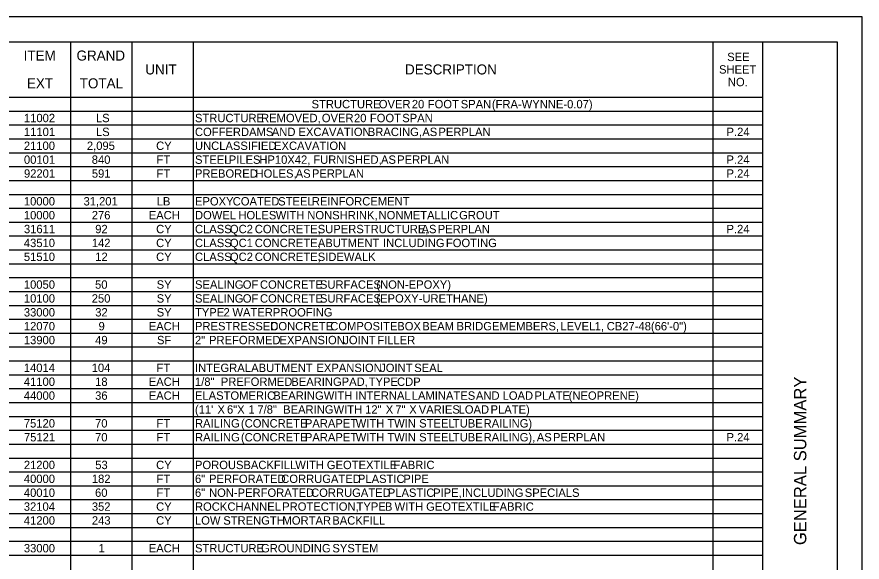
# Model space of a CAD drawing. Extents: x 0 to 34, y 0 to 22.
# Drawn here: x 16.94 to 34, y 11 to 22 of the extents above; entities that cross this region are included whole.
import ezdxf

# ---------------------------------------------------------------- set-up
doc = ezdxf.new("R2010")
doc.units = 0
for name, color, linetype in [('SH_Border', 7, 'Continuous'), ('SH_Cut_Line', 7, 'Continuous'), ('SH_Data', 7, 'Continuous')]:
    doc.layers.add(name, color=color, linetype=linetype)

msp = doc.modelspace()

# ---------------------------------------------------------------- linework, layer by layer
at = {"layer": 'SH_Border'}
msp.add_line((32, 0.5), (32, 21.5), dxfattribs=at)
msp.add_lwpolyline([(1.5, 21.5), (33.5, 21.5), (33.5, 0.5), (1.5, 0.5)], close=True, dxfattribs=at)
at = {"layer": 'SH_Cut_Line'}
msp.add_lwpolyline([(0, 0), (34, 0), (34, 22), (0, 22)], close=True, dxfattribs=at)
at = {"layer": 'SH_Data'}
for p, q in [((16.799, 21.5), (19.27, 21.5)), ((18.035, 0.502), (18.035, 21.5)), ((19.27, 21.5), (20.505, 21.5)), ((19.27, 0.502), (19.27, 21.5)), ((20.505, 21.5), (30.995, 21.5)), ((20.505, 0.502), (20.505, 21.5)), ((30.995, 21.5), (32, 21.5)), ((30.995, 0.502), (30.995, 21.5)), ((32, 0.502), (32, 21.5)), ((13.555, 20.38), (32, 20.38)), ((19.27, 20.38), (32, 20.38)), ((1.5, 20.1), (32, 20.1)), ((1.5, 19.82), (32, 19.82)), ((1.5, 19.54), (32, 19.54)), ((1.5, 19.26), (32, 19.26)), ((1.5, 18.98), (32, 18.98)), ((1.5, 18.7), (32, 18.7)), ((1.5, 18.42), (32, 18.42)), ((1.5, 18.14), (32, 18.14)), ((1.5, 17.86), (32, 17.86)), ((1.5, 17.58), (32, 17.58)), ((1.5, 17.3), (32, 17.3)), ((1.5, 17.021), (32, 17.021)), ((1.5, 16.741), (32, 16.741)), ((1.5, 16.461), (32, 16.461)), ((1.5, 16.181), (32, 16.181)), ((1.5, 15.901), (32, 15.901)), ((1.5, 15.621), (32, 15.621)), ((1.5, 15.341), (32, 15.341)), ((1.5, 15.061), (32, 15.061)), ((1.5, 14.781), (32, 14.781)), ((1.5, 14.501), (32, 14.501)), ((1.5, 14.221), (32, 14.221)), ((1.5, 13.941), (32, 13.941)), ((1.5, 13.661), (32, 13.661)), ((1.5, 13.381), (32, 13.381)), ((1.5, 13.101), (32, 13.101)), ((1.5, 12.821), (32, 12.821)), ((1.5, 12.541), (32, 12.541)), ((1.5, 12.261), (32, 12.261)), ((1.5, 11.981), (32, 11.981)), ((1.5, 11.701), (32, 11.701)), ((1.5, 11.421), (32, 11.421)), ((1.5, 11.141), (32, 11.141))]:
    msp.add_line(p, q, dxfattribs=at)

# ---------------------------------------------------------------- texts
for s, height, p in [('ITEM', 0.2027, (17.081, 21.119)), ('GRAND', 0.2027, (18.148, 21.119)), ('SEE', 0.1689, (31.278, 21.109)), ('UNIT', 0.2027, (19.536, 20.839)), ('DESCRIPTION', 0.20269, (24.777, 20.839)), ('SHEET', 0.1689, (31.113, 20.856)), ('EXT', 0.2027, (17.147, 20.559)), ('TOTAL', 0.2027, (18.213, 20.559)), ('NO.', 0.1689, (31.292, 20.602)), ('STRUCTURE', 0.1689, (22.891, 20.156)), (' OVER', 0.1689, (24.185, 20.156)), (' 20', 0.1689, (24.851, 20.156)), (' FOOT', 0.1689, (25.173, 20.156)), (' SPAN', 0.1689, (25.838, 20.156)), (' (FRA-WYNNE-0.07)', 0.16891, (26.466, 20.156)), ('11002', 0.1689, (17.087, 19.876)), ('LS', 0.1689, (18.54, 19.876)), ('STRUCTURE', 0.1689, (20.538, 19.876)), (' REMOVED,', 0.1689, (21.808, 19.876)), (' OVER', 0.1689, (23.035, 19.876)), (' 20', 0.1689, (23.684, 19.876)), (' FOOT', 0.1689, (24.005, 19.876)), (' SPAN', 0.1689, (24.658, 19.876)), ('11101', 0.1689, (17.087, 19.596)), ('LS', 0.1689, (18.54, 19.596)), ('COFFERDAMS', 0.1689, (20.538, 19.596)), (' AND', 0.1689, (22.026, 19.596)), (' EXCAVATION', 0.16891, (22.564, 19.596)), (' BRACING,', 0.1689, (23.963, 19.596)), (' AS', 0.1689, (25.062, 19.596)), (' PER', 0.1689, (25.388, 19.596)), (' PLAN', 0.1689, (25.85, 19.596)), ('P.24', 0.1689, (31.264, 19.596)), ('21100', 0.1689, (17.085, 19.316)), ('2,095', 0.1689, (18.357, 19.316)), ('CY', 0.1689, (19.754, 19.316)), ('UNCLASSIFIED', 0.16891, (20.538, 19.316)), (' EXCAVATION', 0.16891, (22.071, 19.316)), ('00101', 0.1689, (17.087, 19.036)), ('840', 0.1689, (18.455, 19.036)), ('FT', 0.1689, (19.762, 19.036)), ('STEEL', 0.1689, (20.538, 19.036)), (' PILES', 0.1689, (21.157, 19.036)), (' HP10X42,', 0.1689, (21.774, 19.036)), (' FURNISHED,', 0.16891, (22.863, 19.036)), (' AS', 0.1689, (24.229, 19.036)), (' PER', 0.1689, (24.556, 19.036)), (' PLAN', 0.1689, (25.018, 19.036)), ('P.24', 0.1689, (31.264, 19.036)), ('92201', 0.1689, (17.087, 18.756)), ('591', 0.1689, (18.457, 18.756)), ('FT', 0.1689, (19.762, 18.756)), ('PREBORED', 0.1689, (20.538, 18.756)), (' HOLES,', 0.1689, (21.697, 18.756)), (' AS', 0.1689, (22.508, 18.756)), (' PER', 0.1689, (22.835, 18.756)), (' PLAN', 0.1689, (23.297, 18.756)), ('P.24', 0.1689, (31.264, 18.756)), ('10000', 0.1689, (17.085, 18.196)), ('31,201', 0.1689, (18.289, 18.196)), ('LB', 0.1689, (19.765, 18.196)), ('EPOXY', 0.1689, (20.538, 18.196)), (' COATED', 0.1689, (21.237, 18.196)), (' STEEL', 0.1689, (22.154, 18.196)), (' REINFORCEMENT', 0.16891, (22.834, 18.196)), ('10000', 0.1689, (17.085, 17.916)), ('276', 0.1689, (18.455, 17.916)), ('EACH', 0.1689, (19.605, 17.916)), ('DOWEL', 0.1689, (20.538, 17.916)), (' HOLES', 0.1689, (21.351, 17.916)), (' WITH', 0.1689, (22.105, 17.916)), (' NONSHRINK,', 0.16891, (22.742, 17.916)), (' NONMETALLIC', 0.16891, (24.18, 17.916)), (' GROUT', 0.1689, (25.806, 17.916)), ('31611', 0.1689, (17.087, 17.636)), ('92', 0.1689, (18.525, 17.636)), ('CY', 0.1689, (19.754, 17.636)), ('CLASS', 0.1689, (20.538, 17.636)), (' QC2', 0.1689, (21.18, 17.636)), (' CONCRETE,', 0.1689, (21.682, 17.636)), (' SUPERSTRUCTURE,', 0.16891, (22.953, 17.636)), (' AS', 0.1689, (25.047, 17.636)), (' PER', 0.1689, (25.374, 17.636)), (' PLAN', 0.1689, (25.836, 17.636)), ('P.24', 0.1689, (31.264, 17.636)), ('43510', 0.1689, (17.085, 17.356)), ('142', 0.1689, (18.457, 17.356)), ('CY', 0.1689, (19.754, 17.356)), ('CLASS', 0.1689, (20.538, 17.356)), (' QC1', 0.1689, (21.18, 17.356)), (' CONCRETE,', 0.1689, (21.682, 17.356)), (' ABUTMENT', 0.1689, (22.954, 17.356)), (' INCLUDING', 0.1689, (24.27, 17.356)), (' FOOTING', 0.1689, (25.539, 17.356)), ('51510', 0.1689, (17.085, 17.076)), ('12', 0.1689, (18.525, 17.076)), ('CY', 0.1689, (19.754, 17.076)), ('CLASS', 0.1689, (20.538, 17.076)), (' QC2', 0.1689, (21.18, 17.076)), (' CONCRETE,', 0.1689, (21.682, 17.076)), (' SIDEWALK', 0.1689, (22.953, 17.076)), ('10050', 0.1689, (17.085, 16.516)), ('50', 0.1689, (18.522, 16.516)), ('SY', 0.1689, (19.765, 16.516)), ('SEALING', 0.1689, (20.538, 16.516)), (' OF', 0.1689, (21.44, 16.516)), (' CONCRETE', 0.1689, (21.787, 16.516)), (' SURFACES', 0.1689, (22.997, 16.516)), (' (NON-EPOXY)', 0.16891, (24.136, 16.516)), ('10100', 0.1689, (17.085, 16.236)), ('250', 0.1689, (18.455, 16.236)), ('SY', 0.1689, (19.765, 16.236)), ('SEALING', 0.1689, (20.538, 16.236)), (' OF', 0.1689, (21.44, 16.236)), (' CONCRETE', 0.1689, (21.787, 16.236)), (' SURFACES', 0.1689, (22.997, 16.236)), (' (EPOXY-URETHANE)', 0.16891, (24.136, 16.236)), ('33000', 0.1689, (17.085, 15.956)), ('32', 0.1689, (18.525, 15.956)), ('SY', 0.1689, (19.765, 15.956)), ('TYPE', 0.1689, (20.538, 15.956)), (' 2', 0.1689, (21.051, 15.956)), (' WATERPROOFING', 0.16891, (21.231, 15.956)), ('12070', 0.1689, (17.085, 15.676)), ('9', 0.169, (18.592, 15.676)), ('EACH', 0.1689, (19.605, 15.676)), ('PRESTRESSED', 0.16891, (20.538, 15.676)), (' CONCRETE', 0.1689, (21.995, 15.676)), (' COMPOSITE', 0.1689, (23.205, 15.676)), (' BOX', 0.1689, (24.557, 15.676)), (' BEAM', 0.1689, (25.062, 15.676)), (' BRIDGE', 0.1689, (25.753, 15.676)), (' MEMBERS,', 0.1689, (26.617, 15.676)), (' LEVEL', 0.1689, (27.849, 15.676)), (' 1,', 0.1689, (28.541, 15.676)), (' CB27-48(66\'-0")', 0.16891, (28.784, 15.676)), ('13900', 0.1689, (17.085, 15.396)), ('49', 0.1689, (18.524, 15.396)), ('SF', 0.1689, (19.771, 15.396)), ('2"', 0.1689, (20.538, 15.396)), (' PREFORMED', 0.1689, (20.759, 15.396)), (' EXPANSION', 0.1689, (22.181, 15.396)), (' JOINT', 0.1689, (23.468, 15.396)), (' FILLER', 0.1689, (24.155, 15.396)), ('14014', 0.1689, (17.084, 14.836)), ('104', 0.1689, (18.454, 14.836)), ('FT', 0.1689, (19.762, 14.836)), ('INTEGRAL', 0.1689, (20.538, 14.836)), (' ABUTMENT', 0.1689, (21.609, 14.836)), (' EXPANSION', 0.1689, (22.926, 14.836)), (' JOINT', 0.1689, (24.212, 14.836)), (' SEAL', 0.1689, (24.9, 14.836)), ('41100', 0.1689, (17.085, 14.556)), ('18', 0.1689, (18.523, 14.556)), ('EACH', 0.1689, (19.605, 14.556)), ('1/8"', 0.1689, (20.538, 14.556)), (' PREFORMED', 0.1689, (20.997, 14.556)), (' BEARING', 0.1689, (22.419, 14.556)), (' PAD,', 0.1689, (23.436, 14.556)), (' TYPE', 0.1689, (23.98, 14.556)), (' CDP', 0.1689, (24.553, 14.556)), ('44000', 0.1689, (17.085, 14.276)), ('36', 0.1689, (18.523, 14.276)), ('EACH', 0.1689, (19.605, 14.276)), ('ELASTOMERIC', 0.16891, (20.538, 14.276)), (' BEARING', 0.1689, (22.056, 14.276)), (' WITH', 0.1689, (23.074, 14.276)), (' INTERNAL', 0.1689, (23.711, 14.276)), (' LAMINATES', 0.1689, (24.85, 14.276)), (' AND', 0.1689, (26.145, 14.276)), (' LOAD', 0.1689, (26.683, 14.276)), (' PLATE', 0.1689, (27.327, 14.276)), (' (NEOPRENE)', 0.16891, (28.016, 14.276)), ("(11'", 0.1689, (20.538, 13.996)), (' X', 0.1689, (20.929, 13.996)), (' 6"X', 0.1689, (21.121, 13.996)), (' 1', 0.1689, (21.554, 13.996)), (' 7/8"', 0.1689, (21.735, 13.996)), (' BEARING', 0.1689, (22.254, 13.996)), (' WITH', 0.1689, (23.272, 13.996)), (' 12"', 0.1689, (23.909, 13.996)), (' X', 0.1689, (24.325, 13.996)), (' 7"', 0.1689, (24.517, 13.996)), (' X', 0.1689, (24.799, 13.996)), (' VARIES', 0.1689, (24.991, 13.996)), (' LOAD', 0.1689, (25.795, 13.996)), (' PLATE)', 0.1689, (26.44, 13.996)), ('75120', 0.1689, (17.085, 13.716)), ('70', 0.1689, (18.522, 13.716)), ('FT', 0.1689, (19.762, 13.716)), ('RAILING', 0.1689, (20.538, 13.716)), (' (CONCRETE', 0.1689, (21.403, 13.716)), (' PARAPET', 0.1689, (22.693, 13.716)), (' WITH', 0.1689, (23.719, 13.716)), (' TWIN', 0.1689, (24.356, 13.716)), (' STEEL', 0.1689, (24.999, 13.716)), (' TUBE', 0.1689, (25.679, 13.716)), (' RAILING)', 0.1689, (26.3, 13.716)), ('75121', 0.1689, (17.087, 13.436)), ('70', 0.1689, (18.522, 13.436)), ('FT', 0.1689, (19.762, 13.436)), ('RAILING', 0.1689, (20.538, 13.436)), (' (CONCRETE', 0.1689, (21.403, 13.436)), (' PARAPET', 0.1689, (22.693, 13.436)), (' WITH', 0.1689, (23.719, 13.436)), (' TWIN', 0.1689, (24.356, 13.436)), (' STEEL', 0.1689, (24.999, 13.436)), (' TUBE', 0.1689, (25.679, 13.436)), (' RAILING),', 0.1689, (26.3, 13.436)), (' AS', 0.1689, (27.373, 13.436)), (' PER', 0.1689, (27.7, 13.436)), (' PLAN', 0.1689, (28.162, 13.436)), ('P.24', 0.1689, (31.264, 13.436)), ('21200', 0.1689, (17.085, 12.877)), ('53', 0.1689, (18.525, 12.877)), ('CY', 0.1689, (19.754, 12.877)), ('POROUS', 0.1689, (20.538, 12.877)), (' BACKFILL', 0.1689, (21.453, 12.877)), (' WITH', 0.1689, (22.499, 12.877)), (' GEOTEXTILE', 0.16891, (23.136, 12.877)), (' FABRIC', 0.1689, (24.481, 12.877)), ('40000', 0.1689, (17.085, 12.597)), ('182', 0.1689, (18.457, 12.597)), ('FT', 0.1689, (19.762, 12.597)), ('6"', 0.1689, (20.538, 12.597)), (' PERFORATED', 0.16891, (20.759, 12.597)), (' CORRUGATED', 0.16891, (22.216, 12.597)), (' PLASTIC', 0.1689, (23.764, 12.597)), (' PIPE', 0.1689, (24.68, 12.597)), ('40010', 0.1689, (17.085, 12.317)), ('60', 0.1689, (18.522, 12.317)), ('FT', 0.1689, (19.762, 12.317)), ('6"', 0.1689, (20.538, 12.317)), (' NON-PERFORATED', 0.16891, (20.759, 12.317)), (' CORRUGATED', 0.16891, (22.818, 12.317)), (' PLASTIC', 0.1689, (24.366, 12.317)), (' PIPE,', 0.1689, (25.281, 12.317)), (' INCLUDING', 0.1689, (25.861, 12.317)), (' SPECIALS', 0.1689, (27.13, 12.317)), ('32104', 0.1689, (17.084, 12.037)), ('352', 0.1689, (18.457, 12.037)), ('CY', 0.1689, (19.754, 12.037)), ('ROCK', 0.1689, (20.538, 12.037)), (' CHANNEL', 0.1689, (21.13, 12.037)), (' PROTECTION,', 0.16891, (22.235, 12.037)), (' TYPE', 0.1689, (23.736, 12.037)), (' B', 0.1689, (24.309, 12.037)), (' WITH', 0.1689, (24.503, 12.037)), (' GEOTEXTILE', 0.16891, (25.14, 12.037)), (' FABRIC', 0.1689, (26.485, 12.037)), ('41200', 0.1689, (17.085, 11.757)), ('243', 0.1689, (18.458, 11.757)), ('CY', 0.1689, (19.754, 11.757)), ('LOW', 0.1689, (20.538, 11.757)), (' STRENGTH', 0.1689, (21.046, 11.757)), (' MORTAR', 0.1689, (22.242, 11.757)), (' BACKFILL', 0.1689, (23.246, 11.757)), ('33000', 0.1689, (17.085, 11.197)), ('1', 0.169, (18.592, 11.197)), ('EACH', 0.1689, (19.605, 11.197)), ('STRUCTURE', 0.1689, (20.538, 11.197)), (' GROUNDING', 0.1689, (21.808, 11.197)), (' SYSTEM', 0.1689, (23.248, 11.197))]:
    msp.add_text(s, height=height, dxfattribs=at).set_placement(p)
msp.add_text('GENERAL SUMMARY', height=0.25, rotation=90, dxfattribs=at).set_placement((32.875, 11.344))

doc.saveas('drawing.dxf')
